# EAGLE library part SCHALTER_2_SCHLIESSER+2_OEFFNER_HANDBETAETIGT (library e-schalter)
Schalter, 2 Schließer, 2 Öffner
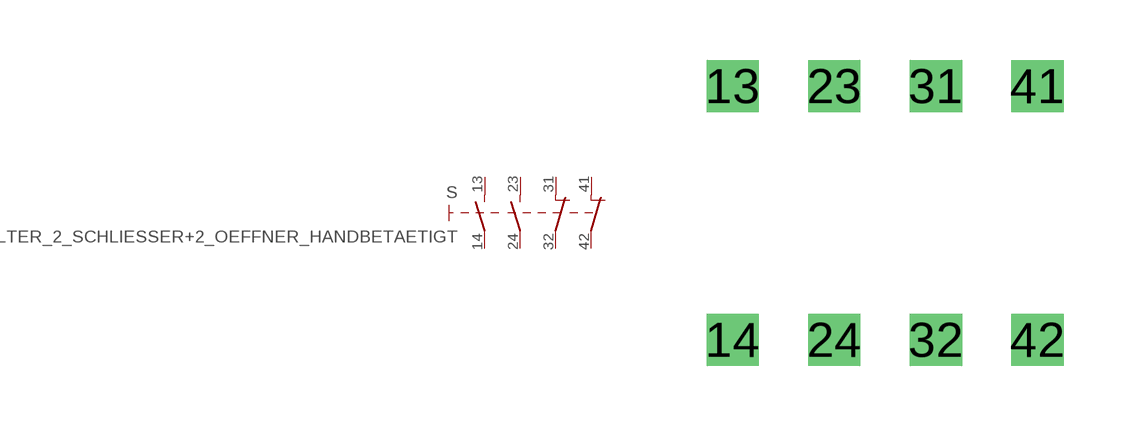
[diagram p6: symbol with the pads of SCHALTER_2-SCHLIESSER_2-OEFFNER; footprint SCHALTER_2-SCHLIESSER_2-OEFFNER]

Designator prefix S

## SCHALTER_2_SCHLIESSER+2_OEFFNER_HANDBETAETIGT  [SCHALTER_2-SCHLIESSER_2-OEFFNER]
13  13  pas
14  14  pas
23  23  pas
24  24  pas
31  31  pas
32  32  pas
41  41  pas
42  42  pas

## Footprint SCHALTER_2-SCHLIESSER_2-OEFFNER (pad centres in mm)
Dummy
drill 0.8 square: 13 -3.81,3.175; 14 -3.81,-3.175; 23 -1.27,3.175; 24 -1.27,-3.175; 31 1.27,3.175; 32 1.27,-3.175; 41 3.81,3.175; 42 3.81,-3.175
